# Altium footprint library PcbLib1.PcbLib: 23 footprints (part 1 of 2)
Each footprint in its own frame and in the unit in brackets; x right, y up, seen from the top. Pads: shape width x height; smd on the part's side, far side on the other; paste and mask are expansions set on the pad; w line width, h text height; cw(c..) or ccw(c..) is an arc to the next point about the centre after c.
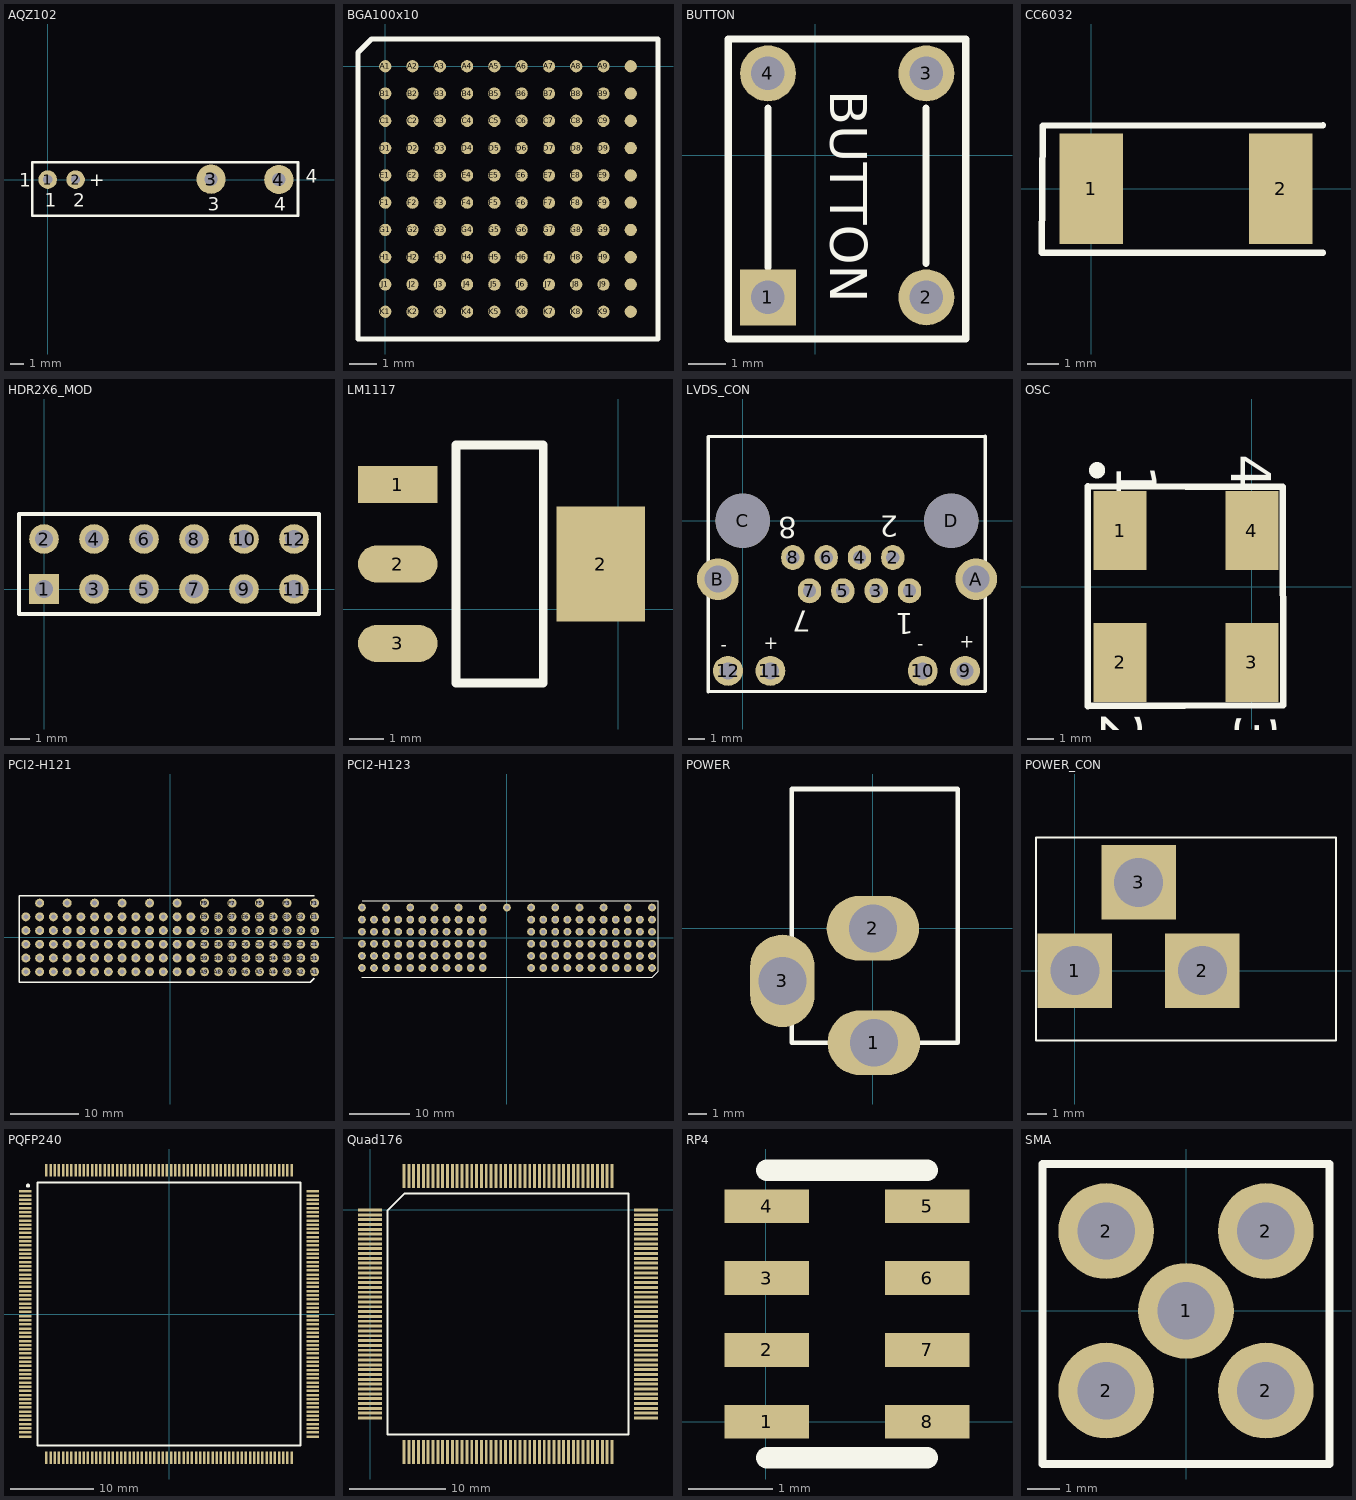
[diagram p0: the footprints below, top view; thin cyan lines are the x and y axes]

## AQZ102 [mm]
pads (4):
  round 1.4 hole 0.7: 1(0,0) 2(2.1,0)
  round 2.2 hole 1: 3(12.3,0.025) 4(17.4,0)
Top Overlay:
  lines w0.203: -1.168,-2.718 18.847,-2.718 18.847,1.295 18.491,1.295 -1.168,1.295 -1.168,-2.718
  text "4" at 19.406,-0.229 h1.02
  text "1" at -2.159,-0.533 h1.02
  text "+" at 3.124,-0.508 h1.02
  text "4" at 17.069,-2.362 h1.02
  text "3" at 12.065,-2.337 h1.02
  text "2" at 1.93,-2.032 h1.02
  text "1" at -0.203,-2.057 h1.02

## BGA100x10 [mm] "for CYP15G0101"
pads (100):
  round 0.45 smd: A1(0,0) A2(1,0) A3(2,0) A4(3,0) A5(4,0) A6(5,0) A7(6,0) A8(7,0) A9(8,0) A10(9,0) B1(0,-1) B2(1,-1) B3(2,-1) B4(3,-1) B5(4,-1) B6(5,-1) B7(6,-1) B8(7,-1) B9(8,-1) B10(9,-1) C1(0,-2) C2(1,-2) C3(2,-2) C4(3,-2) C5(4,-2) C6(5,-2) C7(6,-2) C8(7,-2) C9(8,-2) C10(9,-2) D1(0,-3) D2(1,-3) D3(2,-3) D4(3,-3) D5(4,-3) D6(5,-3) D7(6,-3) D8(7,-3) D9(8,-3) D10(9,-3) E1(0,-4) E2(1,-4) E3(2,-4) E4(3,-4) E5(4,-4) E6(5,-4) E7(6,-4) E8(7,-4) E9(8,-4) E10(9,-4) F1(0,-5) F2(1,-5) F3(2,-5) F4(3,-5) F5(4,-5) F6(5,-5) F7(6,-5) F8(7,-5) F9(8,-5) F10(9,-5) G1(0,-6) G2(1,-6) G3(2,-6) G4(3,-6) G5(4,-6) G6(5,-6) G7(6,-6) G8(7,-6) G9(8,-6) G10(9,-6) H1(0,-7) H2(1,-7) H3(2,-7) H4(3,-7) H5(4,-7) H6(5,-7) H7(6,-7) H8(7,-7) H9(8,-7) H10(9,-7) J1(0,-8) J2(1,-8) J3(2,-8) J4(3,-8) J5(4,-8) J6(5,-8) J7(6,-8) J8(7,-8) J9(8,-8) J10(9,-8) K1(0,-9) K2(1,-9) K3(2,-9) K4(3,-9) K5(4,-9) K6(5,-9) K7(6,-9) K8(7,-9) K9(8,-9) K10(9,-9)
Top Overlay:
  lines w0.2: -1,-10 -1,0.5 -0.5,1 10,1 10,-10 -1,-10

## BUTTON [mm]
pads (4):
  rect 1.5x1.5 hole 0.9: 1(-1.27,-3.81)
  round 1.5 hole 0.9: 2(2.98,-3.81) 3(2.98,2.2) 4(-1.27,2.2)
Top Overlay:
  lines w0.2: -1.27,-2.997 -1.27,1.27 ; 2.972,-2.896 2.972,1.27 ; -2.337,-4.928 4.039,-4.928 4.039,3.124 -2.337,3.124 -2.337,-4.928
  text "BUTTON" at 0.406,1.753 h1

## CC6032 [mm]
pads (2):
  rect 2x3.5 smd: 1(0,0) 2(6,0)
Top Overlay:
  lines w0.2: 7.341,-2.032 -1.564,-2.035 -1.539,1.984 7.341,2.007

## HDR2X6_MOD [mm]
pads (12):
  rect 1.5x1.5 hole 0.9: 1(0,0)
  round 1.5 hole 0.9: 2(0,2.54) 3(2.54,0) 4(2.54,2.54) 5(5.08,0) 6(5.08,2.54) 7(7.62,0) 8(7.62,2.54) 9(10.16,0) 10(10.16,2.54) 11(12.7,0) 12(12.7,2.54)
Top Overlay:
  lines w0.2: -1.27,-1.27 -1.27,3.81 13.97,3.81 13.97,-1.27 -1.27,-1.27

## LM1117 [mil]
pads (4):
  rect 90x42 smd: 1(-250,141)
  oval 90x42 smd: 2(-250,51) 3(-250,-39)
  rect 100x130 smd: 2(-20,51)
Top Overlay:
  lines w10: -99,186 -184,186 -184,-84 -85,-84 -85,186 -97.5,186

## LVDS_CON [mm]
pads (16):
  oval 1.4x1.5 hole 0.8: 1(10,-4.2) 2(9,-2.2) 3(8.001,-4.191) 4(7,-2.2) 5(6,-4.2) 6(5,-2.2) 7(4,-4.2) 8(3,-2.2)
  round 1.8 hole 1.02: 9(13.335,-9) 10(10.795,-9) 11(1.651,-9) 12(-0.889,-9)
  round 2.5 hole 1.63: A(14,-3.5) B(-1.5,-3.5)
  round 3.25 hole 3.25: C(0,0) D(12.5,0)
Top Overlay:
  lines w0.203: -2.083,-10.262 -2.083,0.711 -2.083,5.055 14.554,5.08 14.554,-10.236 -2.083,-10.262
  text "8" at 3.226,0.203 h1.27
  text "2" at 9.322,0.305 h1.27
  text "7" at 4.089,-5.41 h1.27
  text "1" at 10.262,-5.537 h1.27
  text "+" at 13.005,-7.62 h0.76
  text "+" at 1.27,-7.696 h0.76
  text "-" at -1.321,-7.798 h0.76
  text "-" at 10.465,-7.747 h0.76
Bottom Overlay:
  text "7" at 4.115,-5.613 h1.27
  text "8" at 3.327,0.102 h1.27
  text "2" at 9.296,0.508 h1.27
  text "1" at 10.871,-5.715 h1.27
  text "-" at 11.303,-7.62 h0.76
  text "-" at -0.635,-7.849 h0.76
  text "+" at 2.083,-7.798 h0.76
  text "+" at 13.818,-7.798 h0.76

## OSC [mm]
pads (4):
  rect 2x3 smd: 1(-5,2.134) 2(-5,-2.87) 3(0,-2.866) 4(0,2.134)
Top Overlay:
  circle w0.5: c-5.873,4.42 r0.057
  lines w0.254: -6.223,-4.521 -6.223,3.81 1.168,3.785 1.194,-4.496 -6.223,-4.521
  text "4" at -0.787,5.029 h1.52
  text "3" at -0.61,-4.826 h1.52
  text "2" at -5.715,-4.775 h1.52
  text "1" at -5.131,4.623 h1.52

## PCI2-H121 [mm]
pads (121):
  round 1.3 hole 0.7: A1(21,-5) A2(19,-5) A3(17,-5) A4(15,-5) A5(13,-5) A6(11,-5) A7(9,-5) A8(7,-5) A9(5,-5) A10(3,-5) A11(1,-5) A12(-1,-5) A13(-3,-5) A14(-5,-5) A15(-7,-5) A16(-9,-5) A17(-11,-5) A18(-13,-5) A19(-15,-5) A20(-17,-5) A21(-19,-5) A22(-21,-5) B1(21,-3) B2(19,-3) B3(17,-3) B4(15,-3) B5(13,-3) B6(11,-3) B7(9,-3) B8(7,-3) B9(5,-3) B10(3,-3) B11(1,-3) B12(-1,-3) B13(-3,-3) B14(-5,-3) B15(-7,-3) B16(-9,-3) B17(-11,-3) B18(-13,-3) B19(-15,-3) B20(-17,-3) B21(-19,-3) B22(-21,-3) C1(21,-1) C2(19,-1) C3(17,-1) C4(15,-1) C5(13,-1) C6(11,-1) C7(9,-1) C8(7,-1) C9(5,-1) C10(3,-1) C11(1,-1) C12(-1,-1) C13(-3,-1) C14(-5,-1) C15(-7,-1) C16(-9,-1) C17(-11,-1) C18(-13,-1) C19(-15,-1) C20(-17,-1) C21(-19,-1) C22(-21,-1) D1(21,1) D2(19,1) D3(17,1) D4(15,1) D5(13,1) D6(11,1) D7(9,1) D8(7,1) D9(5,1) D10(3,1) D11(1,1) D12(-1,1) D13(-3,1) D14(-5,1) D15(-7,1) D16(-9,1) D17(-11,1) D18(-13,1) D19(-15,1) D20(-17,1) D21(-19,1) D22(-21,1) E1(21,3) E2(19,3) E3(17,3) E4(15,3) E5(13,3) E6(11,3) E7(9,3) E8(7,3) E9(5,3) E10(3,3) E11(1,3) E12(-1,3) E13(-3,3) E14(-5,3) E15(-7,3) E16(-9,3) E17(-11,3) E18(-13,3) E19(-15,3) E20(-17,3) E21(-19,3) E22(-21,3) F1(21,5) F3(17,5) F5(13,5) F7(9,5) F9(5,5) F11(1,5) F13(-3,5) F15(-7,5) F17(-11,5) F19(-15,5) F21(-19,5)
Top Overlay:
  lines w0.2: 20.371,-6.502 -22,-6.5 -22,6.05 20.93,6.045
  lines w0.203: 20.371,-6.502 20.93,-5.944

## PCI2-H123 [mm]
pads (123):
  round 1.3 hole 0.7: A1(24,-5) A2(22,-5) A3(20,-5) A4(18,-5) A5(16,-5) A6(14,-5) A7(12,-5) A8(10,-5) A9(8,-5) A10(6,-5) A11(4,-5) A15(-4,-5) A16(-6,-5) A17(-8,-5) A18(-10,-5) A19(-12,-5) A20(-14,-5) A21(-16,-5) A22(-18,-5) A23(-20,-5) A24(-22,-5) A25(-24,-5) B1(24,-3) B2(22,-3) B3(20,-3) B4(18,-3) B5(16,-3) B6(14,-3) B7(12,-3) B8(10,-3) B9(8,-3) B10(6,-3) B11(4,-3) B15(-4,-3) B16(-6,-3) B17(-8,-3) B18(-10,-3) B19(-12,-3) B20(-14,-3) B21(-16,-3) B22(-18,-3) B23(-20,-3) B24(-22,-3) B25(-24,-3) C1(24,-1) C2(22,-1) C3(20,-1) C4(18,-1) C5(16,-1) C6(14,-1) C7(12,-1) C8(10,-1) C9(8,-1) C10(6,-1) C11(4,-1) C15(-4,-1) C16(-6,-1) C17(-8,-1) C18(-10,-1) C19(-12,-1) C20(-14,-1) C21(-16,-1) C22(-18,-1) C23(-20,-1) C24(-22,-1) C25(-24,-1) D1(24,1) D2(22,1) D3(20,1) D4(18,1) D5(16,1) D6(14,1) D7(12,1) D8(10,1) D9(8,1) D10(6,1) D11(4,1) D15(-4,1) D16(-6,1) D17(-8,1) D18(-10,1) D19(-12,1) D20(-14,1) D21(-16,1) D22(-18,1) D23(-20,1) D24(-22,1) D25(-24,1) E1(24,3) E2(22,3) E3(20,3) E4(18,3) E5(16,3) E6(14,3) E7(12,3) E8(10,3) E9(8,3) E10(6,3) E11(4,3) E15(-4,3) E16(-6,3) E17(-8,3) E18(-10,3) E19(-12,3) E20(-14,3) E21(-16,3) E22(-18,3) E23(-20,3) E24(-22,3) E25(-24,3) F1(24,5) F3(20,5) F5(16,5) F7(12,5) F9(8,5) F11(4,5) F13(0,5) F15(-4,5) F17(-8,5) F19(-12,5) F21(-16,5) F23(-20,5) F25(-24,5)
Top Overlay:
  lines w0.2: -24.028,-6.502 24.028,-6.5 25,-5.528 25,6.1 -23.978,6.096
  lines w0.203: 24.028,-6.5 25,-5.528 25,-5.283

## POWER [mil]
pads (3):
  oval 197x138 hole 102: 1(2.16,-244.32) 2(0.16,-0.32)
  oval 138x197 hole 102: 3(-192.84,-112.32)
Top Overlay:
  lines w10: -172.84,-244.32 -172.84,296.68 181.16,296.68 181.16,-244.32 -170.84,-244.32

## POWER_CON [mm]
pads (3):
  rect 3.8x3.8 hole 2.5: 1(0,0) 2(6.5,0) 3(3.25,4.5)
Top Overlay:
  lines w0.102: -1.981,-3.556 13.31,-3.556 13.31,6.782 -1.981,6.782 -1.981,-3.556

## PQFP240 [mm] "byTX chaned for cyclone FPGA"
pads (240):
  rect 1.5x0.3 smd: 1(-17.3,14.75) 2(-17.3,14.25) 3(-17.3,13.75) 4(-17.3,13.25) 5(-17.3,12.75) 6(-17.3,12.25) 7(-17.3,11.75) 8(-17.3,11.25) 9(-17.3,10.75) 10(-17.3,10.25) 11(-17.3,9.75) 12(-17.3,9.25) 13(-17.3,8.75) 14(-17.3,8.25) 15(-17.3,7.75) 16(-17.3,7.25) 17(-17.3,6.75) 18(-17.3,6.25) 19(-17.3,5.75) 20(-17.3,5.25) 21(-17.3,4.75) 22(-17.3,4.25) 23(-17.3,3.75) 24(-17.3,3.25) 25(-17.3,2.75) 26(-17.3,2.25) 27(-17.3,1.75) 28(-17.3,1.25) 29(-17.3,0.75) 30(-17.3,0.25) 31(-17.3,-0.25) 32(-17.3,-0.75) 33(-17.3,-1.25) 34(-17.3,-1.75) 35(-17.3,-2.25) 36(-17.3,-2.75) 37(-17.3,-3.25) 38(-17.3,-3.75) 39(-17.3,-4.25) 40(-17.3,-4.75) 41(-17.3,-5.25) 42(-17.3,-5.75) 43(-17.3,-6.25) 44(-17.3,-6.75) 45(-17.3,-7.25) 46(-17.3,-7.75) 47(-17.3,-8.25) 48(-17.3,-8.75) 49(-17.3,-9.25) 50(-17.3,-9.75) 51(-17.3,-10.25) 52(-17.3,-10.75) 53(-17.3,-11.25) 54(-17.3,-11.75) 55(-17.3,-12.25) 56(-17.3,-12.75) 57(-17.3,-13.25) 58(-17.3,-13.75) 59(-17.3,-14.25) 60(-17.3,-14.75) 121(17.3,-14.75) 122(17.3,-14.25) 123(17.3,-13.75) 124(17.3,-13.25) 125(17.3,-12.75) 126(17.3,-12.25) 127(17.3,-11.75) 128(17.3,-11.25) 129(17.3,-10.75) 130(17.3,-10.25) 131(17.3,-9.75) 132(17.3,-9.25) 133(17.3,-8.75) 134(17.3,-8.25) 135(17.3,-7.75) 136(17.3,-7.25) 137(17.3,-6.75) 138(17.3,-6.25) 139(17.3,-5.75) 140(17.3,-5.25) 141(17.3,-4.75) 142(17.3,-4.25) 143(17.3,-3.75) 144(17.3,-3.25) 145(17.3,-2.75) 146(17.3,-2.25) 147(17.3,-1.75) 148(17.3,-1.25) 149(17.3,-0.75) 150(17.3,-0.25) 151(17.3,0.25) 152(17.3,0.75) 153(17.3,1.25) 154(17.3,1.75) 155(17.3,2.25) 156(17.3,2.75) 157(17.3,3.25) 158(17.3,3.75) 159(17.3,4.25) 160(17.3,4.75) 161(17.3,5.25) 162(17.3,5.75) 163(17.3,6.25) 164(17.3,6.75) 165(17.3,7.25) 166(17.3,7.75) 167(17.3,8.25) 168(17.3,8.75) 169(17.3,9.25) 170(17.3,9.75) 171(17.3,10.25) 172(17.3,10.75) 173(17.3,11.25) 174(17.3,11.75) 175(17.3,12.25) 176(17.3,12.75) 177(17.3,13.25) 178(17.3,13.75) 179(17.3,14.25) 180(17.3,14.75)
  rect 0.3x1.5 smd: 61(-14.75,-17.3) 62(-14.25,-17.3) 63(-13.75,-17.3) 64(-13.25,-17.3) 65(-12.75,-17.3) 66(-12.25,-17.3) 67(-11.75,-17.3) 68(-11.25,-17.3) 69(-10.75,-17.3) 70(-10.25,-17.3) 71(-9.75,-17.3) 72(-9.25,-17.3) 73(-8.75,-17.3) 74(-8.25,-17.3) 75(-7.75,-17.3) 76(-7.25,-17.3) 77(-6.75,-17.3) 78(-6.25,-17.3) 79(-5.75,-17.3) 80(-5.25,-17.3) 81(-4.75,-17.3) 82(-4.25,-17.3) 83(-3.75,-17.3) 84(-3.25,-17.3) 85(-2.75,-17.3) 86(-2.25,-17.3) 87(-1.75,-17.3) 88(-1.25,-17.3) 89(-0.75,-17.3) 90(-0.25,-17.3) 91(0.25,-17.3) 92(0.75,-17.3) 93(1.25,-17.3) 94(1.75,-17.3) 95(2.25,-17.3) 96(2.75,-17.3) 97(3.25,-17.3) 98(3.75,-17.3) 99(4.25,-17.3) 100(4.75,-17.3) 101(5.25,-17.3) 102(5.75,-17.3) 103(6.25,-17.3) 104(6.75,-17.3) 105(7.25,-17.3) 106(7.75,-17.3) 107(8.25,-17.3) 108(8.75,-17.3) 109(9.25,-17.3) 110(9.75,-17.3) 111(10.25,-17.3) 112(10.75,-17.3) 113(11.25,-17.3) 114(11.75,-17.3) 115(12.25,-17.3) 116(12.75,-17.3) 117(13.25,-17.3) 118(13.75,-17.3) 119(14.25,-17.3) 120(14.75,-17.3) 181(14.75,17.3) 182(14.25,17.3) 183(13.75,17.3) 184(13.25,17.3) 185(12.75,17.3) 186(12.25,17.3) 187(11.75,17.3) 188(11.25,17.3) 189(10.75,17.3) 190(10.25,17.3) 191(9.75,17.3) 192(9.25,17.3) 193(8.75,17.3) 194(8.25,17.3) 195(7.75,17.3) 196(7.25,17.3) 197(6.75,17.3) 198(6.25,17.3) 199(5.75,17.3) 200(5.25,17.3) 201(4.75,17.3) 202(4.25,17.3) 203(3.75,17.3) 204(3.25,17.3) 205(2.75,17.3) 206(2.25,17.3) 207(1.75,17.3) 208(1.25,17.3) 209(0.75,17.3) 210(0.25,17.3) 211(-0.25,17.3) 212(-0.75,17.3) 213(-1.25,17.3) 214(-1.75,17.3) 215(-2.25,17.3) 216(-2.75,17.3) 217(-3.25,17.3) 218(-3.75,17.3) 219(-4.25,17.3) 220(-4.75,17.3) 221(-5.25,17.3) 222(-5.75,17.3) 223(-6.25,17.3) 224(-6.75,17.3) 225(-7.25,17.3) 226(-7.75,17.3) 227(-8.25,17.3) 228(-8.75,17.3) 229(-9.25,17.3) 230(-9.75,17.3) 231(-10.25,17.3) 232(-10.75,17.3) 233(-11.25,17.3) 234(-11.75,17.3) 235(-12.25,17.3) 236(-12.75,17.3) 237(-13.25,17.3) 238(-13.75,17.3) 239(-14.25,17.3) 240(-14.75,17.3)
Top Overlay:
  circle w0.25: c-16.975,15.45 r0.125
  lines w0.2: -15.825,-15.825 -15.825,15.825 15.825,15.825 15.825,-15.825 -15.825,-15.825

## Quad176 [mm]
pads (176):
  rect 2.5x0.3 smd: 1(0,0) 2(0,-0.5) 3(0,-1) 4(0,-1.5) 5(0,-2) 6(0,-2.5) 7(0,-3) 8(0,-3.5) 9(0,-4) 10(0,-4.5) 11(0,-5) 12(0,-5.5) 13(0,-6) 14(0,-6.5) 15(0,-7) 16(0,-7.5) 17(0,-8) 18(0,-8.5) 19(0,-9) 20(0,-9.5) 21(0,-10) 22(0,-10.5) 23(0,-11) 24(0,-11.5) 25(0,-12) 26(0,-12.5) 27(0,-13) 28(0,-13.5) 29(0,-14) 30(0,-14.5) 31(0,-15) 32(0,-15.5) 33(0,-16) 34(0,-16.5) 35(0,-17) 36(0,-17.5) 37(0,-18) 38(0,-18.5) 39(0,-19) 40(0,-19.5) 41(0,-20) 42(0,-20.5) 43(0,-21) 44(0,-21.5) 89(28.5,-21.5) 90(28.5,-21) 91(28.5,-20.5) 92(28.5,-20) 93(28.5,-19.5) 94(28.5,-19) 95(28.5,-18.5) 96(28.5,-18) 97(28.5,-17.5) 98(28.5,-17) 99(28.5,-16.5) 100(28.5,-16) 101(28.5,-15.5) 102(28.5,-15) 103(28.5,-14.5) 104(28.5,-14) 105(28.5,-13.5) 106(28.5,-13) 107(28.5,-12.5) 108(28.5,-12) 109(28.5,-11.5) 110(28.5,-11) 111(28.5,-10.5) 112(28.5,-10) 113(28.5,-9.5) 114(28.5,-9) 115(28.5,-8.5) 116(28.5,-8) 117(28.5,-7.5) 118(28.5,-7) 119(28.5,-6.5) 120(28.5,-6) 121(28.5,-5.5) 122(28.5,-5) 123(28.5,-4.5) 124(28.5,-4) 125(28.5,-3.5) 126(28.5,-3) 127(28.5,-2.5) 128(28.5,-2) 129(28.5,-1.5) 130(28.5,-1) 131(28.5,-0.5) 132(28.5,0)
  rect 0.3x2.5 smd: 45(3.5,-25) 46(4,-25) 47(4.5,-25) 48(5,-25) 49(5.5,-25) 50(6,-25) 51(6.5,-25) 52(7,-25) 53(7.5,-25) 54(8,-25) 55(8.5,-25) 56(9,-25) 57(9.5,-25) 58(10,-25) 59(10.5,-25) 60(11,-25) 61(11.5,-25) 62(12,-25) 63(12.5,-25) 64(13,-25) 65(13.5,-25) 66(14,-25) 67(14.5,-25) 68(15,-25) 69(15.5,-25) 70(16,-25) 71(16.5,-25) 72(17,-25) 73(17.5,-25) 74(18,-25) 75(18.5,-25) 76(19,-25) 77(19.5,-25) 78(20,-25) 79(20.5,-25) 80(21,-25) 81(21.5,-25) 82(22,-25) 83(22.5,-25) 84(23,-25) 85(23.5,-25) 86(24,-25) 87(24.5,-25) 88(25,-25) 133(25,3.5) 134(24.5,3.5) 135(24,3.5) 136(23.5,3.5) 137(23,3.5) 138(22.5,3.5) 139(22,3.5) 140(21.5,3.5) 141(21,3.5) 142(20.5,3.5) 143(20,3.5) 144(19.5,3.5) 145(19,3.5) 146(18.5,3.5) 147(18,3.5) 148(17.5,3.5) 149(17,3.5) 150(16.5,3.5) 151(16,3.5) 152(15.5,3.5) 153(15,3.5) 154(14.5,3.5) 155(14,3.5) 156(13.5,3.5) 157(13,3.5) 158(12.5,3.5) 159(12,3.5) 160(11.5,3.5) 161(11,3.5) 162(10.5,3.5) 163(10,3.5) 164(9.5,3.5) 165(9,3.5) 166(8.5,3.5) 167(8,3.5) 168(7.5,3.5) 169(7,3.5) 170(6.5,3.5) 171(6,3.5) 172(5.5,3.5) 173(5,3.5) 174(4.5,3.5) 175(4,3.5) 176(3.5,3.5)
Top Overlay:
  lines w0.2: 1.785,-23.215 1.785,-0.07 3.57,1.715 26.715,1.715 26.715,-23.215 1.785,-23.215

## RP4 [mm]
pads (8):
  rect 1x0.4 smd: 1(0.011,0.002) 2(0.011,0.852) 3(0.011,1.702) 4(0.011,2.552) 5(1.911,2.552) 6(1.911,1.702) 7(1.911,0.852) 8(1.911,0.002)
Top Overlay:
  lines w0.254: 0.011,-0.423 1.911,-0.423 ; 0.011,2.977 1.911,2.977

## SMA [mm]
pads (5):
  round 3 hole 1.8: 1(0,0) 2(-2.5,-2.5) 2(-2.5,2.5) 2(2.5,-2.5) 2(2.5,2.5)
Top Overlay:
  lines w0.254: -4.5,-4.8 4.5,-4.8 4.5,4.6 -4.5,4.6 -4.5,-4.8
